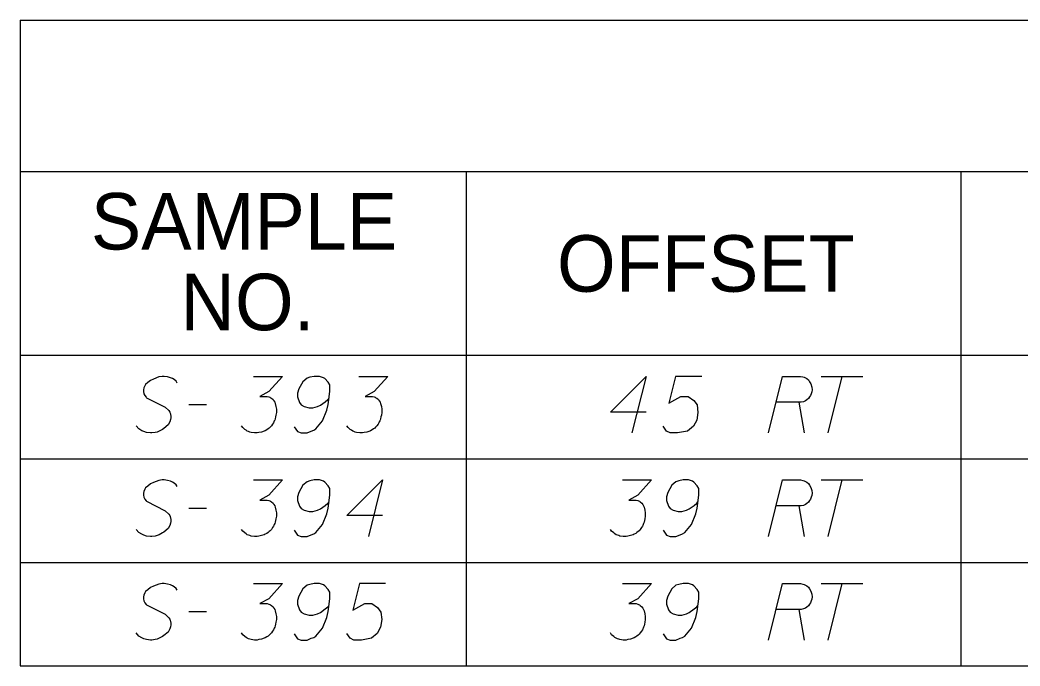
# Model space of a CAD drawing. Extents: x 2074207 to 2076812, y 516372 to 523312.
# Drawn here: x 2076260.6 to 2076345.6, y 517407.3 to 517462.2 of the extents above; entities that cross this region are included whole.
import ezdxf

# ---------------------------------------------------------------- set-up
doc = ezdxf.new("R2010")
doc.units = 0
for name, color, linetype in [('Prop DirtTable_ Soil Test Results - Outline (Major)', 7, 'Continuous'), ('Prop DirtTable_ Soil Test Results - Outline (Minor)', 7, 'Continuous'), ('Prop DirtTable_ Soil Test Results - Tx (Header - Small)', 7, 'Continuous'), ('Prop DirtTable_ Soil Test Results - Tx (Sample Data)', 7, 'Continuous')]:
    doc.layers.add(name, color=color, linetype=linetype)

msp = doc.modelspace()

# ---------------------------------------------------------------- linework, layer by layer
at = {"layer": 'Prop DirtTable_ Soil Test Results - Outline (Major)'}
for p, q in [((2076260.609, 517462.179), (2076260.609, 517433.694)), ((2076260.609, 517462.179), (2076811.903, 517462.179)), ((2076260.609, 517433.694), (2076260.609, 517424.894)), ((2076260.609, 517433.694), (2076811.903, 517433.694)), ((2076260.609, 517433.694), (2076811.903, 517433.694)), ((2076260.609, 517424.894), (2076260.609, 517416.094)), ((2076260.609, 517416.094), (2076260.609, 517407.294)), ((2076260.609, 517407.294), (2076811.903, 517407.294))]:
    msp.add_line(p, q, dxfattribs=at)
at = {"layer": 'Prop DirtTable_ Soil Test Results - Outline (Minor)'}
for p, q in [((2076260.609, 517449.294), (2076811.903, 517449.294)), ((2076298.545, 517449.294), (2076298.545, 517424.894)), ((2076340.594, 517449.294), (2076340.594, 517424.894)), ((2076260.609, 517424.894), (2076811.903, 517424.894)), ((2076260.609, 517424.894), (2076811.903, 517424.894)), ((2076298.546, 517424.894), (2076298.546, 517416.094)), ((2076340.594, 517424.894), (2076340.594, 517416.094)), ((2076260.609, 517416.094), (2076811.903, 517416.094)), ((2076260.609, 517416.094), (2076811.903, 517416.094)), ((2076298.546, 517416.094), (2076298.546, 517407.294)), ((2076340.594, 517416.094), (2076340.594, 517407.294)), ((2076260.609, 517407.294), (2076811.903, 517407.294))]:
    msp.add_line(p, q, dxfattribs=at)
at = {"layer": 'Prop DirtTable_ Soil Test Results - Tx (Sample Data)'}
for points in [[(2076273.968, 517431.331), (2076273.897, 517431.482), (2076273.721, 517431.633), (2076273.58, 517431.709), (2076273.403, 517431.785), (2076273.157, 517431.86), (2076272.874, 517431.898), (2076272.698, 517431.898), (2076272.416, 517431.86), (2076271.957, 517431.671), (2076271.71, 517431.558), (2076271.463, 517431.369), (2076271.287, 517431.218), (2076271.216, 517431.104), (2076271.146, 517430.915), (2076271.111, 517430.764), (2076271.111, 517430.613), (2076271.146, 517430.424), (2076271.216, 517430.273), (2076271.322, 517430.122), (2076271.358, 517430.084), (2076272.945, 517429.29), (2076273.262, 517428.988), (2076273.333, 517428.874), (2076273.368, 517428.799), (2076273.439, 517428.534), (2076273.439, 517428.383), (2076273.403, 517428.232), (2076273.333, 517428.043), (2076273.192, 517427.778), (2076272.839, 517427.476), (2076272.733, 517427.4), (2076272.451, 517427.249), (2076272.275, 517427.174), (2076272.098, 517427.136), (2076271.816, 517427.098), (2076271.71, 517427.098), (2076271.358, 517427.136), (2076271.146, 517427.211), (2076270.969, 517427.287), (2076270.723, 517427.438), (2076270.476, 517427.703)], [(2076280.459, 517431.898), (2076282.928, 517431.898), (2076281.764, 517430.613), (2076280.988, 517430.197), (2076281.623, 517430.197), (2076281.764, 517430.159), (2076281.834, 517430.122), (2076281.905, 517430.084), (2076281.975, 517430.046), (2076282.117, 517429.933), (2076282.187, 517429.819), (2076282.258, 517429.706), (2076282.293, 517429.592), (2076282.363, 517429.328), (2076282.399, 517429.101), (2076282.399, 517428.988), (2076282.399, 517428.837), (2076282.363, 517428.61), (2076282.328, 517428.459), (2076282.293, 517428.307), (2076282.258, 517428.194), (2076282.222, 517428.118), (2076282.187, 517428.043), (2076282.152, 517427.967), (2076282.081, 517427.854), (2076281.975, 517427.703), (2076281.87, 517427.589), (2076281.799, 517427.514), (2076281.693, 517427.438), (2076281.587, 517427.363), (2076281.446, 517427.287), (2076281.376, 517427.249), (2076281.129, 517427.174), (2076280.917, 517427.136), (2076280.776, 517427.098), (2076280.529, 517427.098), (2076280.247, 517427.136), (2076280.141, 517427.174), (2076280.035, 517427.211), (2076279.929, 517427.249), (2076279.824, 517427.325), (2076279.718, 517427.4), (2076279.541, 517427.552), (2076279.436, 517427.703)], [(2076283.916, 517427.627), (2076284.198, 517427.211), (2076284.515, 517427.098), (2076285.009, 517427.098), (2076285.362, 517427.249), (2076285.574, 517427.325), (2076285.75, 517427.438), (2076286.314, 517428.118), (2076286.702, 517429.026), (2076286.808, 517429.517), (2076286.949, 517430.613), (2076286.949, 517431.18), (2076286.808, 517431.407), (2076286.526, 517431.709), (2076286.42, 517431.785), (2076286.067, 517431.898), (2076285.609, 517431.898), (2076285.256, 517431.822), (2076285.009, 517431.747), (2076284.656, 517431.444), (2076284.304, 517430.84), (2076284.198, 517430.462), (2076284.198, 517430.159), (2076284.374, 517429.668), (2076284.515, 517429.479), (2076284.762, 517429.328), (2076285.186, 517429.215), (2076285.503, 517429.215), (2076285.891, 517429.328), (2076286.138, 517429.441), (2076286.561, 517429.744), (2076286.773, 517429.933), (2076286.879, 517430.046)], [(2076289.419, 517431.898), (2076291.888, 517431.898), (2076290.724, 517430.613), (2076289.948, 517430.197), (2076290.583, 517430.197), (2076290.724, 517430.159), (2076290.794, 517430.122), (2076290.865, 517430.084), (2076290.935, 517430.046), (2076291.077, 517429.933), (2076291.147, 517429.819), (2076291.218, 517429.706), (2076291.253, 517429.592), (2076291.323, 517429.328), (2076291.359, 517429.101), (2076291.359, 517428.988), (2076291.359, 517428.837), (2076291.323, 517428.61), (2076291.288, 517428.459), (2076291.253, 517428.307), (2076291.218, 517428.194), (2076291.182, 517428.118), (2076291.147, 517428.043), (2076291.112, 517427.967), (2076291.041, 517427.854), (2076290.935, 517427.703), (2076290.83, 517427.589), (2076290.759, 517427.514), (2076290.653, 517427.438), (2076290.547, 517427.363), (2076290.406, 517427.287), (2076290.336, 517427.249), (2076290.089, 517427.174), (2076289.877, 517427.136), (2076289.736, 517427.098), (2076289.489, 517427.098), (2076289.207, 517427.136), (2076289.101, 517427.174), (2076288.995, 517427.211), (2076288.889, 517427.249), (2076288.784, 517427.325), (2076288.678, 517427.4), (2076288.501, 517427.552), (2076288.396, 517427.703)], [(2076313.829, 517428.874), (2076310.796, 517428.874), (2076313.829, 517431.898), (2076312.63, 517427.098)], [(2076318.556, 517431.898), (2076316.334, 517431.898), (2076315.769, 517429.63), (2076316.792, 517430.197), (2076317.392, 517430.197), (2076317.886, 517429.857), (2076318.168, 517429.479), (2076318.239, 517428.837), (2076318.133, 517428.194), (2076317.851, 517427.665), (2076317.357, 517427.249), (2076316.51, 517427.098), (2076315.875, 517427.098), (2076315.558, 517427.249), (2076315.276, 517427.665)], [(2076324.236, 517427.098), (2076325.435, 517431.898), (2076326.952, 517431.898), (2076327.163, 517431.86), (2076327.269, 517431.822), (2076327.481, 517431.709), (2076327.622, 517431.596), (2076327.728, 517431.444), (2076327.834, 517431.255), (2076327.904, 517430.991), (2076327.94, 517430.764), (2076327.904, 517430.575), (2076327.869, 517430.424), (2076327.798, 517430.273), (2076327.728, 517430.159), (2076327.622, 517430.008), (2076327.481, 517429.895), (2076327.375, 517429.819), (2076327.199, 517429.744), (2076327.022, 517429.706), (2076324.906, 517429.706)], [(2076328.716, 517431.898), (2076332.243, 517431.898)], [(2076330.479, 517431.898), (2076329.28, 517427.098)], [(2076326.811, 517429.706), (2076327.269, 517427.098)], [(2076274.956, 517429.517), (2076276.472, 517429.517)], [(2076273.968, 517422.531), (2076273.897, 517422.682), (2076273.721, 517422.833), (2076273.58, 517422.909), (2076273.403, 517422.985), (2076273.157, 517423.06), (2076272.874, 517423.098), (2076272.698, 517423.098), (2076272.416, 517423.06), (2076271.957, 517422.871), (2076271.71, 517422.758), (2076271.463, 517422.569), (2076271.287, 517422.418), (2076271.216, 517422.304), (2076271.146, 517422.115), (2076271.111, 517421.964), (2076271.111, 517421.813), (2076271.146, 517421.624), (2076271.216, 517421.473), (2076271.322, 517421.322), (2076271.358, 517421.284), (2076272.945, 517420.49), (2076273.262, 517420.188), (2076273.333, 517420.074), (2076273.368, 517419.999), (2076273.439, 517419.734), (2076273.439, 517419.583), (2076273.403, 517419.432), (2076273.333, 517419.243), (2076273.192, 517418.978), (2076272.839, 517418.676), (2076272.733, 517418.6), (2076272.451, 517418.449), (2076272.275, 517418.374), (2076272.098, 517418.336), (2076271.816, 517418.298), (2076271.71, 517418.298), (2076271.358, 517418.336), (2076271.146, 517418.411), (2076270.969, 517418.487), (2076270.723, 517418.638), (2076270.476, 517418.903)], [(2076280.459, 517423.098), (2076282.928, 517423.098), (2076281.764, 517421.813), (2076280.988, 517421.397), (2076281.623, 517421.397), (2076281.764, 517421.359), (2076281.834, 517421.322), (2076281.905, 517421.284), (2076281.975, 517421.246), (2076282.117, 517421.133), (2076282.187, 517421.019), (2076282.258, 517420.906), (2076282.293, 517420.792), (2076282.363, 517420.528), (2076282.399, 517420.301), (2076282.399, 517420.188), (2076282.399, 517420.037), (2076282.363, 517419.81), (2076282.328, 517419.659), (2076282.293, 517419.507), (2076282.258, 517419.394), (2076282.222, 517419.318), (2076282.187, 517419.243), (2076282.152, 517419.167), (2076282.081, 517419.054), (2076281.975, 517418.903), (2076281.87, 517418.789), (2076281.799, 517418.714), (2076281.693, 517418.638), (2076281.587, 517418.563), (2076281.446, 517418.487), (2076281.376, 517418.449), (2076281.129, 517418.374), (2076280.917, 517418.336), (2076280.776, 517418.298), (2076280.529, 517418.298), (2076280.247, 517418.336), (2076280.141, 517418.374), (2076280.035, 517418.411), (2076279.929, 517418.449), (2076279.824, 517418.525), (2076279.718, 517418.6), (2076279.541, 517418.752), (2076279.436, 517418.903)], [(2076283.916, 517418.827), (2076284.198, 517418.411), (2076284.515, 517418.298), (2076285.009, 517418.298), (2076285.362, 517418.449), (2076285.574, 517418.525), (2076285.75, 517418.638), (2076286.314, 517419.318), (2076286.702, 517420.226), (2076286.808, 517420.717), (2076286.949, 517421.813), (2076286.949, 517422.38), (2076286.808, 517422.607), (2076286.526, 517422.909), (2076286.42, 517422.985), (2076286.067, 517423.098), (2076285.609, 517423.098), (2076285.256, 517423.022), (2076285.009, 517422.947), (2076284.656, 517422.644), (2076284.304, 517422.04), (2076284.198, 517421.662), (2076284.198, 517421.359), (2076284.374, 517420.868), (2076284.515, 517420.679), (2076284.762, 517420.528), (2076285.186, 517420.415), (2076285.503, 517420.415), (2076285.891, 517420.528), (2076286.138, 517420.641), (2076286.561, 517420.944), (2076286.773, 517421.133), (2076286.879, 517421.246)], [(2076291.429, 517420.074), (2076288.396, 517420.074), (2076291.429, 517423.098), (2076290.23, 517418.298)], [(2076311.819, 517423.098), (2076314.288, 517423.098), (2076313.124, 517421.813), (2076312.348, 517421.397), (2076312.983, 517421.397), (2076313.124, 517421.359), (2076313.194, 517421.322), (2076313.265, 517421.284), (2076313.335, 517421.246), (2076313.477, 517421.133), (2076313.547, 517421.019), (2076313.618, 517420.906), (2076313.653, 517420.792), (2076313.723, 517420.528), (2076313.759, 517420.301), (2076313.759, 517420.188), (2076313.759, 517420.037), (2076313.723, 517419.81), (2076313.688, 517419.659), (2076313.653, 517419.507), (2076313.618, 517419.394), (2076313.582, 517419.318), (2076313.547, 517419.243), (2076313.512, 517419.167), (2076313.441, 517419.054), (2076313.335, 517418.903), (2076313.23, 517418.789), (2076313.159, 517418.714), (2076313.053, 517418.638), (2076312.947, 517418.563), (2076312.806, 517418.487), (2076312.736, 517418.449), (2076312.489, 517418.374), (2076312.277, 517418.336), (2076312.136, 517418.298), (2076311.889, 517418.298), (2076311.607, 517418.336), (2076311.501, 517418.374), (2076311.395, 517418.411), (2076311.289, 517418.449), (2076311.184, 517418.525), (2076311.078, 517418.6), (2076310.901, 517418.752), (2076310.796, 517418.903)], [(2076315.276, 517418.827), (2076315.558, 517418.411), (2076315.875, 517418.298), (2076316.369, 517418.298), (2076316.722, 517418.449), (2076316.934, 517418.525), (2076317.11, 517418.638), (2076317.674, 517419.318), (2076318.062, 517420.226), (2076318.168, 517420.717), (2076318.309, 517421.813), (2076318.309, 517422.38), (2076318.168, 517422.607), (2076317.886, 517422.909), (2076317.78, 517422.985), (2076317.427, 517423.098), (2076316.969, 517423.098), (2076316.616, 517423.022), (2076316.369, 517422.947), (2076316.016, 517422.644), (2076315.664, 517422.04), (2076315.558, 517421.662), (2076315.558, 517421.359), (2076315.734, 517420.868), (2076315.875, 517420.679), (2076316.122, 517420.528), (2076316.546, 517420.415), (2076316.863, 517420.415), (2076317.251, 517420.528), (2076317.498, 517420.641), (2076317.921, 517420.944), (2076318.133, 517421.133), (2076318.239, 517421.246)], [(2076324.236, 517418.298), (2076325.435, 517423.098), (2076326.952, 517423.098), (2076327.163, 517423.06), (2076327.269, 517423.022), (2076327.481, 517422.909), (2076327.622, 517422.796), (2076327.728, 517422.644), (2076327.834, 517422.455), (2076327.904, 517422.191), (2076327.94, 517421.964), (2076327.904, 517421.775), (2076327.869, 517421.624), (2076327.798, 517421.473), (2076327.728, 517421.359), (2076327.622, 517421.208), (2076327.481, 517421.095), (2076327.375, 517421.019), (2076327.199, 517420.944), (2076327.022, 517420.906), (2076324.906, 517420.906)], [(2076328.716, 517423.098), (2076332.243, 517423.098)], [(2076330.479, 517423.098), (2076329.28, 517418.298)], [(2076274.956, 517420.717), (2076276.472, 517420.717)], [(2076326.811, 517420.906), (2076327.269, 517418.298)], [(2076273.968, 517413.731), (2076273.897, 517413.882), (2076273.721, 517414.033), (2076273.58, 517414.109), (2076273.403, 517414.185), (2076273.157, 517414.26), (2076272.874, 517414.298), (2076272.698, 517414.298), (2076272.416, 517414.26), (2076271.957, 517414.071), (2076271.71, 517413.958), (2076271.463, 517413.769), (2076271.287, 517413.618), (2076271.216, 517413.504), (2076271.146, 517413.315), (2076271.111, 517413.164), (2076271.111, 517413.013), (2076271.146, 517412.824), (2076271.216, 517412.673), (2076271.322, 517412.522), (2076271.358, 517412.484), (2076272.945, 517411.69), (2076273.262, 517411.388), (2076273.333, 517411.274), (2076273.368, 517411.199), (2076273.439, 517410.934), (2076273.439, 517410.783), (2076273.403, 517410.632), (2076273.333, 517410.443), (2076273.192, 517410.178), (2076272.839, 517409.876), (2076272.733, 517409.8), (2076272.451, 517409.649), (2076272.275, 517409.574), (2076272.098, 517409.536), (2076271.816, 517409.498), (2076271.71, 517409.498), (2076271.358, 517409.536), (2076271.146, 517409.611), (2076270.969, 517409.687), (2076270.723, 517409.838), (2076270.476, 517410.103)], [(2076280.459, 517414.298), (2076282.928, 517414.298), (2076281.764, 517413.013), (2076280.988, 517412.597), (2076281.623, 517412.597), (2076281.764, 517412.559), (2076281.834, 517412.522), (2076281.905, 517412.484), (2076281.975, 517412.446), (2076282.117, 517412.333), (2076282.187, 517412.219), (2076282.258, 517412.106), (2076282.293, 517411.992), (2076282.363, 517411.728), (2076282.399, 517411.501), (2076282.399, 517411.388), (2076282.399, 517411.237), (2076282.363, 517411.01), (2076282.328, 517410.859), (2076282.293, 517410.707), (2076282.258, 517410.594), (2076282.222, 517410.518), (2076282.187, 517410.443), (2076282.152, 517410.367), (2076282.081, 517410.254), (2076281.975, 517410.103), (2076281.87, 517409.989), (2076281.799, 517409.914), (2076281.693, 517409.838), (2076281.587, 517409.763), (2076281.446, 517409.687), (2076281.376, 517409.649), (2076281.129, 517409.574), (2076280.917, 517409.536), (2076280.776, 517409.498), (2076280.529, 517409.498), (2076280.247, 517409.536), (2076280.141, 517409.574), (2076280.035, 517409.611), (2076279.929, 517409.649), (2076279.824, 517409.725), (2076279.718, 517409.8), (2076279.541, 517409.952), (2076279.436, 517410.103)], [(2076283.916, 517410.027), (2076284.198, 517409.611), (2076284.515, 517409.498), (2076285.009, 517409.498), (2076285.362, 517409.649), (2076285.574, 517409.725), (2076285.75, 517409.838), (2076286.314, 517410.518), (2076286.702, 517411.426), (2076286.808, 517411.917), (2076286.949, 517413.013), (2076286.949, 517413.58), (2076286.808, 517413.807), (2076286.526, 517414.109), (2076286.42, 517414.185), (2076286.067, 517414.298), (2076285.609, 517414.298), (2076285.256, 517414.222), (2076285.009, 517414.147), (2076284.656, 517413.844), (2076284.304, 517413.24), (2076284.198, 517412.862), (2076284.198, 517412.559), (2076284.374, 517412.068), (2076284.515, 517411.879), (2076284.762, 517411.728), (2076285.186, 517411.615), (2076285.503, 517411.615), (2076285.891, 517411.728), (2076286.138, 517411.841), (2076286.561, 517412.144), (2076286.773, 517412.333), (2076286.879, 517412.446)], [(2076291.676, 517414.298), (2076289.454, 517414.298), (2076288.889, 517412.03), (2076289.912, 517412.597), (2076290.512, 517412.597), (2076291.006, 517412.257), (2076291.288, 517411.879), (2076291.359, 517411.237), (2076291.253, 517410.594), (2076290.971, 517410.065), (2076290.477, 517409.649), (2076289.63, 517409.498), (2076288.995, 517409.498), (2076288.678, 517409.649), (2076288.396, 517410.065)], [(2076311.819, 517414.298), (2076314.288, 517414.298), (2076313.124, 517413.013), (2076312.348, 517412.597), (2076312.983, 517412.597), (2076313.124, 517412.559), (2076313.194, 517412.522), (2076313.265, 517412.484), (2076313.335, 517412.446), (2076313.477, 517412.333), (2076313.547, 517412.219), (2076313.618, 517412.106), (2076313.653, 517411.992), (2076313.723, 517411.728), (2076313.759, 517411.501), (2076313.759, 517411.388), (2076313.759, 517411.237), (2076313.723, 517411.01), (2076313.688, 517410.859), (2076313.653, 517410.707), (2076313.618, 517410.594), (2076313.582, 517410.518), (2076313.547, 517410.443), (2076313.512, 517410.367), (2076313.441, 517410.254), (2076313.335, 517410.103), (2076313.23, 517409.989), (2076313.159, 517409.914), (2076313.053, 517409.838), (2076312.947, 517409.763), (2076312.806, 517409.687), (2076312.736, 517409.649), (2076312.489, 517409.574), (2076312.277, 517409.536), (2076312.136, 517409.498), (2076311.889, 517409.498), (2076311.607, 517409.536), (2076311.501, 517409.574), (2076311.395, 517409.611), (2076311.289, 517409.649), (2076311.184, 517409.725), (2076311.078, 517409.8), (2076310.901, 517409.952), (2076310.796, 517410.103)], [(2076315.276, 517410.027), (2076315.558, 517409.611), (2076315.875, 517409.498), (2076316.369, 517409.498), (2076316.722, 517409.649), (2076316.934, 517409.725), (2076317.11, 517409.838), (2076317.674, 517410.518), (2076318.062, 517411.426), (2076318.168, 517411.917), (2076318.309, 517413.013), (2076318.309, 517413.58), (2076318.168, 517413.807), (2076317.886, 517414.109), (2076317.78, 517414.185), (2076317.427, 517414.298), (2076316.969, 517414.298), (2076316.616, 517414.222), (2076316.369, 517414.147), (2076316.016, 517413.844), (2076315.664, 517413.24), (2076315.558, 517412.862), (2076315.558, 517412.559), (2076315.734, 517412.068), (2076315.875, 517411.879), (2076316.122, 517411.728), (2076316.546, 517411.615), (2076316.863, 517411.615), (2076317.251, 517411.728), (2076317.498, 517411.841), (2076317.921, 517412.144), (2076318.133, 517412.333), (2076318.239, 517412.446)], [(2076324.236, 517409.498), (2076325.435, 517414.298), (2076326.952, 517414.298), (2076327.163, 517414.26), (2076327.269, 517414.222), (2076327.481, 517414.109), (2076327.622, 517413.996), (2076327.728, 517413.844), (2076327.834, 517413.655), (2076327.904, 517413.391), (2076327.94, 517413.164), (2076327.904, 517412.975), (2076327.869, 517412.824), (2076327.798, 517412.673), (2076327.728, 517412.559), (2076327.622, 517412.408), (2076327.481, 517412.295), (2076327.375, 517412.219), (2076327.199, 517412.144), (2076327.022, 517412.106), (2076324.906, 517412.106)], [(2076328.716, 517414.298), (2076332.243, 517414.298)], [(2076330.479, 517414.298), (2076329.28, 517409.498)], [(2076274.956, 517411.917), (2076276.472, 517411.917)], [(2076326.811, 517412.106), (2076327.269, 517409.498)]]:
    msp.add_lwpolyline(points, dxfattribs=at)

# ---------------------------------------------------------------- texts
at = {"layer": 'Prop DirtTable_ Soil Test Results - Tx (Header - Small)'}
for s, p in [('SAMPLE', (2076266.632, 517442.68)), ('OFFSET', (2076306.254, 517439.094)), ('NO.', (2076274.244, 517435.823))]:
    msp.add_text(s, height=4.8, dxfattribs=at).set_placement(p)

doc.saveas('drawing.dxf')
